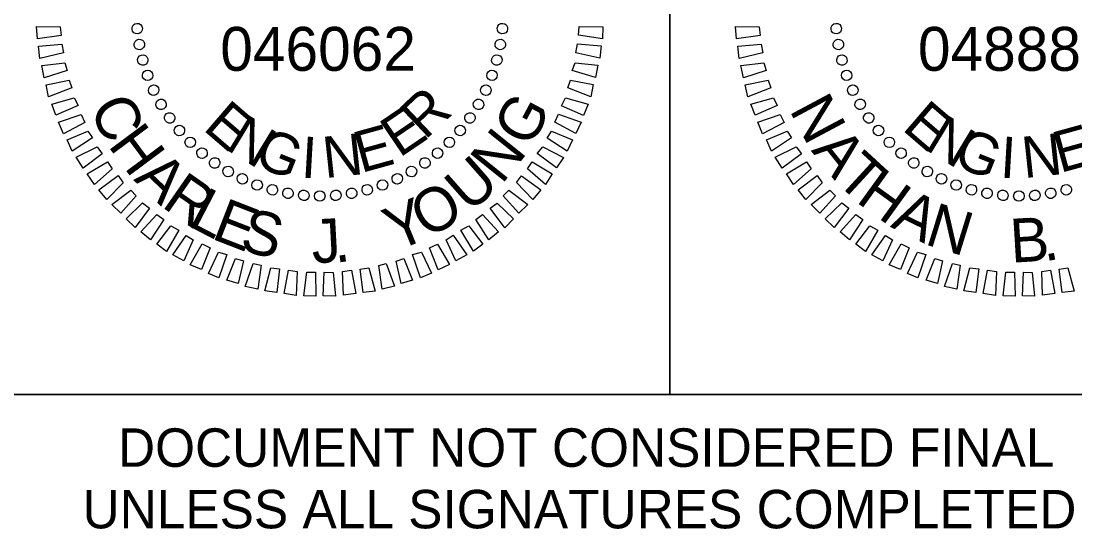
# Model space of a CAD drawing. Extents: x 1648862 to 1650715, y 820691 to 821791.
# Drawn here: x 1650336.4 to 1650487.2, y 821609.3 to 821681.9 of the extents above; entities that cross this region are included whole.
import ezdxf

# ---------------------------------------------------------------- set-up
doc = ezdxf.new("R2010")
doc.units = 0
for name, color, linetype in [('Default', 7, 'Continuous'), ('Old_Level_2', 7, 'Continuous'), ('Sheet Profile CELL', 7, 'Continuous'), ('Sheet Sticker Exception Certification CELL', 7, 'Continuous')]:
    doc.layers.add(name, color=color, linetype=linetype)

msp = doc.modelspace()

# ---------------------------------------------------------------- linework, layer by layer
at = {"layer": 'Old_Level_2'}
for p, q in [((1650353.02, 821680.8), (1650353.02, 821680.8)), ((1650405.32, 821680.77), (1650405.32, 821680.77)), ((1650453.07, 821680.8), (1650453.07, 821680.8)), ((1650353.38, 821678.56), (1650353.38, 821678.56)), ((1650404.99, 821678.52), (1650404.99, 821678.52)), ((1650453.42, 821678.56), (1650453.42, 821678.56)), ((1650353.84, 821676.26), (1650353.84, 821676.26)), ((1650404.56, 821676.31), (1650404.56, 821676.31)), ((1650453.88, 821676.26), (1650453.88, 821676.26)), ((1650354.5, 821674.08), (1650354.5, 821674.08)), ((1650403.87, 821674.1), (1650403.87, 821674.1)), ((1650454.55, 821674.08), (1650454.55, 821674.08)), ((1650355.37, 821672), (1650355.37, 821672)), ((1650402.96, 821672), (1650402.96, 821672)), ((1650455.42, 821672), (1650455.42, 821672)), ((1650356.46, 821669.98), (1650356.46, 821669.98)), ((1650401.95, 821669.94), (1650401.95, 821669.94)), ((1650456.5, 821669.98), (1650456.5, 821669.98)), ((1650357.69, 821668.02), (1650357.69, 821668.02)), ((1650400.68, 821668.03), (1650400.68, 821668.03)), ((1650457.74, 821668.02), (1650457.74, 821668.02)), ((1650359.03, 821666.21), (1650359.03, 821666.21)), ((1650399.3, 821666.18), (1650399.3, 821666.18)), ((1650459.08, 821666.21), (1650459.08, 821666.21)), ((1650360.63, 821664.51), (1650360.63, 821664.51)), ((1650397.76, 821664.53), (1650397.76, 821664.53)), ((1650460.68, 821664.51), (1650460.68, 821664.51)), ((1650362.28, 821662.97), (1650362.28, 821662.97)), ((1650396.06, 821662.93), (1650396.06, 821662.93)), ((1650462.32, 821662.97), (1650462.32, 821662.97)), ((1650364.13, 821661.59), (1650364.13, 821661.59)), ((1650394.25, 821661.59), (1650394.25, 821661.59)), ((1650464.18, 821661.59), (1650464.18, 821661.59)), ((1650366.04, 821660.32), (1650366.04, 821660.32)), ((1650392.29, 821660.36), (1650392.29, 821660.36)), ((1650466.08, 821660.32), (1650466.08, 821660.32)), ((1650368.09, 821659.31), (1650368.09, 821659.31)), ((1650370.2, 821658.4), (1650370.2, 821658.4)), ((1650388.19, 821658.4), (1650388.19, 821658.4)), ((1650390.27, 821659.28), (1650390.27, 821659.28)), ((1650468.14, 821659.31), (1650468.14, 821659.31)), ((1650470.25, 821658.4), (1650470.25, 821658.4)), ((1650372.41, 821657.71), (1650372.41, 821657.71)), ((1650374.61, 821657.28), (1650374.61, 821657.28)), ((1650376.87, 821656.95), (1650376.87, 821656.95)), ((1650379.17, 821656.83), (1650379.17, 821656.83)), ((1650381.47, 821656.93), (1650381.47, 821656.93)), ((1650383.71, 821657.28), (1650383.71, 821657.28)), ((1650386.01, 821657.74), (1650386.01, 821657.74)), ((1650472.46, 821657.71), (1650472.46, 821657.71)), ((1650474.66, 821657.28), (1650474.66, 821657.28)), ((1650476.92, 821656.95), (1650476.92, 821656.95)), ((1650479.22, 821656.83), (1650479.22, 821656.83)), ((1650481.52, 821656.93), (1650481.52, 821656.93)), ((1650483.76, 821657.28), (1650483.76, 821657.28)), ((1650486.05, 821657.74), (1650486.05, 821657.74))]:
    msp.add_line(p, q, dxfattribs=at)
for points in [[(1650342.16, 821679.83), (1650338.77, 821679.35), (1650338.64, 821681.12), (1650342.04, 821681.08)], [(1650416.3, 821681.12), (1650419.7, 821681.07), (1650419.62, 821679.35), (1650416.21, 821679.86)], [(1650442.21, 821679.83), (1650438.82, 821679.35), (1650438.68, 821681.12), (1650442.08, 821681.08)], [(1650342.52, 821677.32), (1650339.14, 821676.53), (1650338.95, 821678.3), (1650342.29, 821678.57)], [(1650416.08, 821678.61), (1650419.43, 821678.35), (1650419.25, 821676.57), (1650415.84, 821677.35)], [(1650442.57, 821677.32), (1650439.18, 821676.53), (1650438.99, 821678.3), (1650442.34, 821678.57)], [(1650343.04, 821674.82), (1650339.76, 821673.77), (1650339.41, 821675.54), (1650342.7, 821675.91)], [(1650415.71, 821675.93), (1650418.96, 821675.57), (1650418.62, 821673.79), (1650415.31, 821674.83)], [(1650443.08, 821674.82), (1650439.81, 821673.77), (1650439.46, 821675.54), (1650442.75, 821675.91)], [(1650343.71, 821672.32), (1650340.38, 821671.06), (1650340.04, 821672.78), (1650343.32, 821673.41)], [(1650415.07, 821673.41), (1650418.32, 821672.79), (1650417.99, 821671.06), (1650414.67, 821672.31)], [(1650443.75, 821672.32), (1650440.43, 821671.06), (1650440.08, 821672.78), (1650443.37, 821673.41)], [(1650344.59, 821669.83), (1650341.42, 821668.41), (1650340.82, 821670.02), (1650344.04, 821670.92)], [(1650414.33, 821670.89), (1650417.59, 821670), (1650416.94, 821668.37), (1650413.78, 821669.78)], [(1650444.63, 821669.83), (1650441.47, 821668.41), (1650440.86, 821670.02), (1650444.09, 821670.92)], [(1650345.57, 821667.39), (1650342.51, 821665.76), (1650341.8, 821667.42), (1650345.03, 821668.53)], [(1650413.33, 821668.57), (1650416.59, 821667.42), (1650415.83, 821665.79), (1650412.82, 821667.41)], [(1650445.62, 821667.39), (1650442.56, 821665.76), (1650441.85, 821667.42), (1650445.07, 821668.53)], [(1650346.66, 821665.16), (1650343.76, 821663.28), (1650343.05, 821664.88), (1650346.01, 821666.14)], [(1650412.32, 821666.15), (1650415.33, 821664.89), (1650414.57, 821663.26), (1650411.71, 821665.14)], [(1650446.7, 821665.16), (1650443.81, 821663.28), (1650443.1, 821664.88), (1650446.06, 821666.14)], [(1650348.05, 821662.88), (1650345.32, 821660.84), (1650344.3, 821662.4), (1650347.3, 821663.91)], [(1650411.11, 821663.88), (1650414.06, 821662.36), (1650413.04, 821660.88), (1650410.29, 821662.92)], [(1650448.1, 821662.88), (1650445.37, 821660.84), (1650444.34, 821662.4), (1650447.35, 821663.91)], [(1650349.45, 821660.76), (1650346.93, 821658.52), (1650345.91, 821660.02), (1650348.81, 821661.74)], [(1650409.57, 821661.76), (1650412.43, 821660.03), (1650411.46, 821658.5), (1650408.91, 821660.75)], [(1650449.5, 821660.76), (1650446.97, 821658.52), (1650445.96, 821660.02), (1650448.85, 821661.74)], [(1650351.06, 821658.75), (1650348.69, 821656.35), (1650347.57, 821657.75), (1650350.31, 821659.78)], [(1650408.04, 821659.74), (1650410.8, 821657.75), (1650409.67, 821656.37), (1650407.33, 821658.79)], [(1650451.1, 821658.75), (1650448.74, 821656.35), (1650447.62, 821657.75), (1650450.35, 821659.78)], [(1650352.92, 821656.9), (1650350.71, 821654.4), (1650349.44, 821655.63), (1650352.12, 821657.72)], [(1650406.25, 821657.72), (1650408.95, 821655.63), (1650407.66, 821654.4), (1650405.42, 821656.87)], [(1650452.97, 821656.9), (1650450.76, 821654.4), (1650449.48, 821655.63), (1650452.17, 821657.72)], [(1650354.83, 821655.1), (1650352.74, 821652.35), (1650351.46, 821653.58), (1650353.83, 821655.87)], [(1650404.55, 821655.86), (1650406.89, 821653.6), (1650405.66, 821652.33), (1650403.57, 821655.12)], [(1650454.88, 821655.1), (1650452.78, 821652.35), (1650451.51, 821653.58), (1650453.87, 821655.87)], [(1650356.85, 821653.52), (1650354.96, 821650.61), (1650353.58, 821651.73), (1650355.84, 821654.23)], [(1650402.49, 821654.21), (1650404.78, 821651.74), (1650403.39, 821650.61), (1650401.51, 821653.51)], [(1650456.89, 821653.52), (1650455.01, 821650.61), (1650453.63, 821651.73), (1650455.89, 821654.23)], [(1650359.02, 821651.98), (1650357.24, 821648.92), (1650355.86, 821649.99), (1650357.86, 821652.59)], [(1650400.53, 821652.6), (1650402.51, 821649.97), (1650401.17, 821648.95), (1650399.39, 821651.96)], [(1650459.06, 821651.98), (1650457.29, 821648.92), (1650455.91, 821649.99), (1650457.9, 821652.59)], [(1650361.08, 821650.61), (1650359.72, 821647.6), (1650358.14, 821648.46), (1650360.08, 821651.22)], [(1650398.25, 821651.26), (1650400.24, 821648.47), (1650398.63, 821647.6), (1650397.27, 821650.61)], [(1650461.13, 821650.61), (1650459.77, 821647.6), (1650458.18, 821648.46), (1650460.12, 821651.22)], [(1650363.51, 821649.45), (1650362.25, 821646.34), (1650360.62, 821647.04), (1650362.35, 821650)], [(1650396.03, 821649.96), (1650397.75, 821647.06), (1650396.14, 821646.3), (1650394.88, 821649.47)], [(1650463.55, 821649.45), (1650462.3, 821646.34), (1650460.67, 821647.04), (1650462.39, 821650)], [(1650365.88, 821648.5), (1650364.73, 821645.18), (1650363.26, 821645.78), (1650364.67, 821648.84)], [(1650368.25, 821647.6), (1650367.52, 821644.34), (1650365.89, 821644.83), (1650367.14, 821647.94)], [(1650391.2, 821647.94), (1650392.46, 821644.83), (1650390.84, 821644.33), (1650390.11, 821647.56)], [(1650393.75, 821648.82), (1650395.16, 821645.82), (1650393.6, 821645.16), (1650392.44, 821648.49)], [(1650465.92, 821648.5), (1650464.78, 821645.18), (1650463.3, 821645.78), (1650464.72, 821648.84)], [(1650468.29, 821647.6), (1650467.57, 821644.34), (1650465.94, 821644.83), (1650467.19, 821647.94)], [(1650370.77, 821646.96), (1650370.3, 821643.55), (1650368.52, 821643.94), (1650369.67, 821647.2)], [(1650373.44, 821646.43), (1650373.03, 821643.08), (1650371.3, 821643.31), (1650372.19, 821646.57)], [(1650386.2, 821646.6), (1650387.1, 821643.27), (1650385.37, 821643.08), (1650384.95, 821646.42)], [(1650388.7, 821647.22), (1650389.86, 821643.95), (1650388.09, 821643.55), (1650387.61, 821646.94)], [(1650470.81, 821646.96), (1650470.35, 821643.55), (1650468.57, 821643.94), (1650469.71, 821647.2)], [(1650473.49, 821646.43), (1650473.08, 821643.08), (1650471.35, 821643.31), (1650472.23, 821646.57)], [(1650486.25, 821646.6), (1650487.14, 821643.27), (1650485.42, 821643.08), (1650485, 821646.42)], [(1650375.96, 821646.06), (1650375.81, 821642.65), (1650374.08, 821642.94), (1650374.7, 821646.24)], [(1650378.58, 821645.95), (1650378.64, 821642.55), (1650376.91, 821642.57), (1650377.32, 821645.98)], [(1650381.09, 821645.94), (1650381.41, 821642.54), (1650379.68, 821642.57), (1650379.83, 821645.97)], [(1650383.7, 821646.24), (1650384.33, 821642.91), (1650382.56, 821642.67), (1650382.45, 821646.07)], [(1650476.01, 821646.06), (1650475.86, 821642.65), (1650474.13, 821642.94), (1650474.75, 821646.24)], [(1650478.62, 821645.95), (1650478.68, 821642.55), (1650476.96, 821642.57), (1650477.37, 821645.98)], [(1650481.13, 821645.94), (1650481.46, 821642.54), (1650479.73, 821642.57), (1650479.88, 821645.97)], [(1650483.74, 821646.24), (1650484.38, 821642.91), (1650482.6, 821642.67), (1650482.49, 821646.07)]]:
    msp.add_lwpolyline(points, close=True, dxfattribs=at)
for centre, major_axis in [((1650353.06, 821680.8), (-0.75, -0.066)), ((1650405.31, 821680.8), (0.75, -0.066)), ((1650453.1, 821680.8), (-0.75, -0.066)), ((1650353.36, 821678.53), (-0.742, -0.131)), ((1650405.01, 821678.53), (0.742, -0.131)), ((1650453.4, 821678.53), (-0.742, -0.131)), ((1650353.85, 821676.3), (-0.727, -0.195)), ((1650404.52, 821676.3), (0.727, -0.195)), ((1650453.9, 821676.3), (-0.727, -0.195)), ((1650354.54, 821674.12), (-0.708, -0.258)), ((1650403.83, 821674.12), (0.708, -0.258)), ((1650454.59, 821674.12), (-0.708, -0.258)), ((1650355.41, 821672), (-0.682, -0.318)), ((1650402.95, 821672), (0.682, -0.318)), ((1650455.46, 821672), (-0.682, -0.318)), ((1650356.47, 821669.97), (-0.652, -0.376)), ((1650401.9, 821669.97), (0.652, -0.376)), ((1650456.52, 821669.97), (-0.652, -0.376)), ((1650357.7, 821668.04), (-0.617, -0.432)), ((1650400.67, 821668.04), (0.617, -0.432)), ((1650457.75, 821668.04), (-0.617, -0.432)), ((1650359.09, 821666.23), (-0.577, -0.484)), ((1650399.28, 821666.23), (0.577, -0.484)), ((1650459.14, 821666.23), (-0.577, -0.484)), ((1650360.64, 821664.54), (-0.532, -0.532)), ((1650397.73, 821664.54), (0.532, -0.532)), ((1650460.69, 821664.54), (-0.532, -0.532)), ((1650362.33, 821662.99), (-0.484, -0.577)), ((1650396.04, 821662.99), (0.484, -0.577)), ((1650462.37, 821662.99), (-0.484, -0.577)), ((1650364.14, 821661.6), (-0.432, -0.617)), ((1650394.23, 821661.6), (0.432, -0.617)), ((1650464.19, 821661.6), (-0.432, -0.617)), ((1650366.07, 821660.37), (-0.376, -0.652)), ((1650368.1, 821659.32), (-0.318, -0.682)), ((1650390.27, 821659.32), (0.318, -0.682)), ((1650392.3, 821660.37), (0.376, -0.652)), ((1650466.12, 821660.37), (-0.376, -0.652)), ((1650468.15, 821659.32), (-0.318, -0.682)), ((1650370.21, 821658.44), (-0.258, -0.708)), ((1650372.4, 821657.75), (-0.195, -0.727)), ((1650385.97, 821657.75), (0.195, -0.727)), ((1650388.15, 821658.44), (0.258, -0.708)), ((1650470.26, 821658.44), (-0.258, -0.708)), ((1650472.44, 821657.75), (-0.195, -0.727)), ((1650486.02, 821657.75), (0.195, -0.727)), ((1650374.63, 821657.26), (-0.131, -0.742)), ((1650376.9, 821656.96), (-0.066, -0.75)), ((1650379.18, 821656.86), (0, -0.753)), ((1650381.47, 821656.96), (0.066, -0.75)), ((1650383.74, 821657.26), (0.131, -0.742)), ((1650474.68, 821657.26), (-0.131, -0.742)), ((1650476.95, 821656.96), (-0.066, -0.75)), ((1650479.23, 821656.86), (0, -0.753)), ((1650481.52, 821656.96), (0.066, -0.75)), ((1650483.79, 821657.26), (0.131, -0.742))]:
    msp.add_ellipse(centre, major_axis=major_axis, ratio=0.999708, dxfattribs=at)
at = {"layer": 'Sheet Profile CELL'}
msp.add_line((1650429.28, 821740.97), (1650429.28, 821628.52), dxfattribs=at)
for points in [[(1650329.23, 821740.97), (1650429.28, 821740.97), (1650429.28, 821628.47), (1650329.23, 821628.47)], [(1650429.28, 821740.97), (1650529.28, 821740.97), (1650529.28, 821628.47), (1650429.28, 821628.47)]]:
    msp.add_lwpolyline(points, close=True, dxfattribs=at)
at = {"layer": 'Sheet Sticker Exception Certification CELL'}
msp.add_line((1650329.23, 821628.47), (1650529.27, 821628.47), dxfattribs=at)
msp.add_line((1650329.23, 821628.47), (1650529.27, 821628.47), dxfattribs=at)

# ---------------------------------------------------------------- texts
at = {"layer": 'Default'}
for s, rotation, p in [('C', 297.1999, (1650346.07, 821669.36)), ('G', 61.7998, (1650409.3, 821663.59)), ('N', 298.0773, (1650446.31, 821669.19)), ('H', 306.6436, (1650348.76, 821664.11)), ('N', 51.2288, (1650405.21, 821658.4)), ('A', 308.6891, (1650449.42, 821663.36)), ('T', 317.4354, (1650452.76, 821659.05)), ('A', 316.4834, (1650352.45, 821659.18)), ('U', 41.4347, (1650400.63, 821654.33)), ('R', 325.1961, (1650356.38, 821655.41)), ('H', 324.1633, (1650455.75, 821656.11)), ('L', 332.5683, (1650360.12, 821652.71)), ('O', 30.0413, (1650394.53, 821650.66)), ('A', 334.0411, (1650460.72, 821652.48)), ('E', 338.7525, (1650363.5, 821650.83)), ('Y', 22.2426, (1650390, 821648.88)), ('N', 342.7874, (1650465.58, 821650.01)), ('S', 345.7591, (1650367.55, 821649.16)), ('B', 3.4911, (1650478.14, 821647.31)), ('J', 3.0321, (1650378.14, 821647.23)), ('.', 8.214, (1650381.39, 821647.28)), ('.', 11.1059, (1650482.89, 821647.47))]:
    msp.add_text(s, height=6.27, rotation=rotation, dxfattribs=at).set_placement(p)
at = {"layer": 'Old_Level_2'}
for s, p in [('046062', (1650364.94, 821674.77)), ('048883', (1650464.78, 821674.77))]:
    msp.add_text(s, height=6.275, dxfattribs=at).set_placement(p)
for s, rotation, p in [('R', 43.4814, (1650394.25, 821664.78)), ('E', 319.2769, (1650362.32, 821666.42)), ('E', 319.2769, (1650462.37, 821666.42)), ('E', 34.1241, (1650390.58, 821662.26)), ('N', 328.634, (1650365.51, 821663.65)), ('N', 328.634, (1650465.56, 821663.65)), ('G', 337.9902, (1650369.52, 821661.37)), ('E', 15.4118, (1650385.08, 821660.13)), ('G', 337.9902, (1650469.57, 821661.37)), ('E', 15.4118, (1650485.12, 821660.13)), ('I', 356.7012, (1650376.41, 821659.5)), ('N', 6.0564, (1650379.91, 821659.41)), ('I', 356.7012, (1650476.45, 821659.5)), ('N', 6.0564, (1650479.96, 821659.41))]:
    msp.add_text(s, height=5.9, rotation=rotation, dxfattribs=at).set_placement(p)
at = {"layer": 'Sheet Sticker Exception Certification CELL'}
for s, p in [('DOCUMENT NOT CONSIDERED FINAL', (1650350.3, 821618.13)), ('DOCUMENT NOT CONSIDERED FINAL', (1650350.3, 821618.13)), ('UNLESS ALL SIGNATURES COMPLETED', (1650345.23, 821609.33)), ('UNLESS ALL SIGNATURES COMPLETED', (1650345.23, 821609.33))]:
    msp.add_text(s, height=5.5, dxfattribs=at).set_placement(p)

doc.saveas('drawing.dxf')
